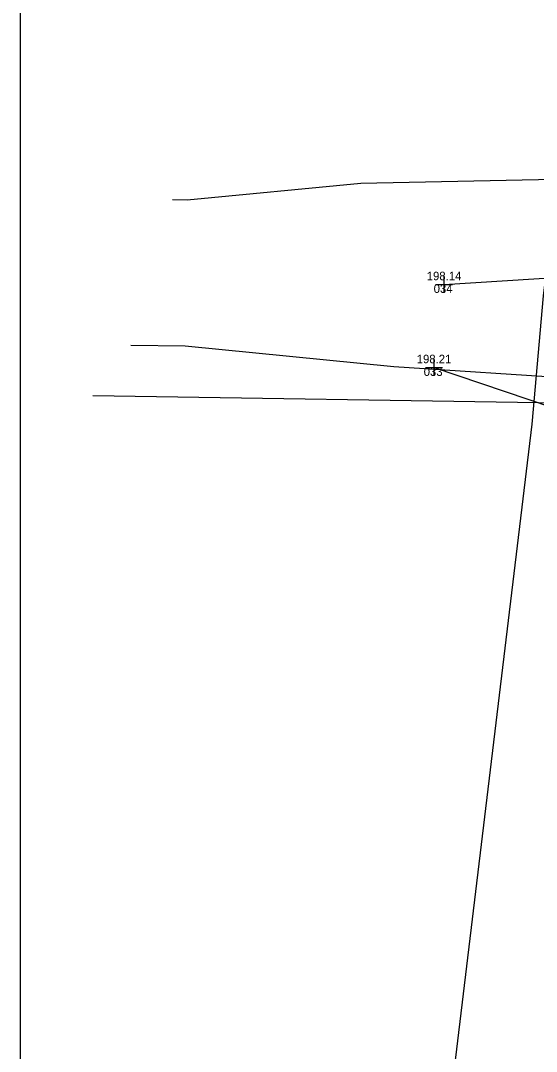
# Model space of a CAD drawing. Extents: x -706655 to -706193, y -1036183 to -1035040.
# Drawn here: x -706654.6 to -706624.1, y -1035149.6 to -1035088.7 of the extents above; entities that cross this region are included whole.
import ezdxf

# ---------------------------------------------------------------- set-up
doc = ezdxf.new("R2010")
doc.units = 0
for name, color, linetype in [('CETIN', 7, 'Continuous'), ('Hranice parcel', 7, 'Continuous'), ('křížky', 7, 'Continuous'), ('Stávající terén', 7, 'Continuous'), ('Vrstva 54', 7, 'Continuous'), ('výšky', 7, 'Continuous'), ('čísla bodu', 7, 'Continuous')]:
    doc.layers.add(name, color=color, linetype=linetype)

msp = doc.modelspace()

# ---------------------------------------------------------------- linework, layer by layer
at = {"layer": 'CETIN'}
msp.add_lwpolyline([(-706632.29, -1035178.176), (-706624.38, -1035112.55), (-706623.72, -1035104.98), (-706623.414, -1035102.598), (-706615.872, -1035043.919)], dxfattribs=at)
at = {"layer": 'Hranice parcel'}
msp.add_line((-706650.337, -1035110.851), (-706620.25, -1035111.32), dxfattribs=at)
for points in [[(-706615.7, -1035096.22), (-706617.34, -1035097.98), (-706634.51, -1035098.34), (-706644.76, -1035099.32), (-706645.624, -1035099.305)], [(-706620.25, -1035111.32), (-706621.7, -1035109.87), (-706632.56, -1035109.17), (-706644.89, -1035107.95), (-706648.091, -1035107.907)]]:
    msp.add_lwpolyline(points, dxfattribs=at)
at = {"layer": 'křížky'}
for p, q in [((-706629.59, -1035104.8), (-706629.59, -1035103.8)), ((-706630.09, -1035104.3), (-706629.09, -1035104.3)), ((-706629.59, -1035104.3), (-706629.59, -1035104.3)), ((-706630.18, -1035109.7), (-706630.18, -1035108.7)), ((-706630.68, -1035109.2), (-706629.68, -1035109.2)), ((-706630.18, -1035109.2), (-706630.18, -1035109.2))]:
    msp.add_line(p, q, dxfattribs=at)
at = {"layer": 'Stávající terén'}
for points in [[(-706629.59, -1035104.3), (-706616.8, -1035103.5), (-706614.08, -1035099.42), (-706611.61, -1035087.02), (-706610.92, -1035075.19)], [(-706630.18, -1035109.2), (-706620.44, -1035112.49), (-706618.86, -1035128.69), (-706620.88, -1035145.19)]]:
    msp.add_lwpolyline(points, dxfattribs=at)
at = {"layer": 'Vrstva 54'}
msp.add_lwpolyline([(-706654.6, -1035040.151), (-706286.789, -1035040.151), (-706286.789, -1035285.37), (-706654.6, -1035285.37)], close=True, dxfattribs=at)
at = {"layer": 'čísla bodu'}
for p, q in [((-706629.59, -1035104.8), (-706629.59, -1035103.8)), ((-706630.09, -1035104.3), (-706629.09, -1035104.3)), ((-706629.59, -1035104.3), (-706629.59, -1035104.3)), ((-706630.18, -1035109.7), (-706630.18, -1035108.7)), ((-706630.68, -1035109.2), (-706629.68, -1035109.2)), ((-706630.18, -1035109.2), (-706630.18, -1035109.2))]:
    msp.add_line(p, q, dxfattribs=at)

# ---------------------------------------------------------------- texts
at = {"layer": 'výšky'}
for s, p in [('198.14', (-706630.612, -1035104.05)), ('198.21', (-706631.203, -1035108.95))]:
    msp.add_text(s, height=0.5, dxfattribs=at).set_placement(p)
at = {"layer": 'čísla bodu'}
for s, p in [('034', (-706630.202, -1035104.8)), ('033', (-706630.792, -1035109.7))]:
    msp.add_text(s, height=0.5, dxfattribs=at).set_placement(p)

doc.saveas('drawing.dxf')
